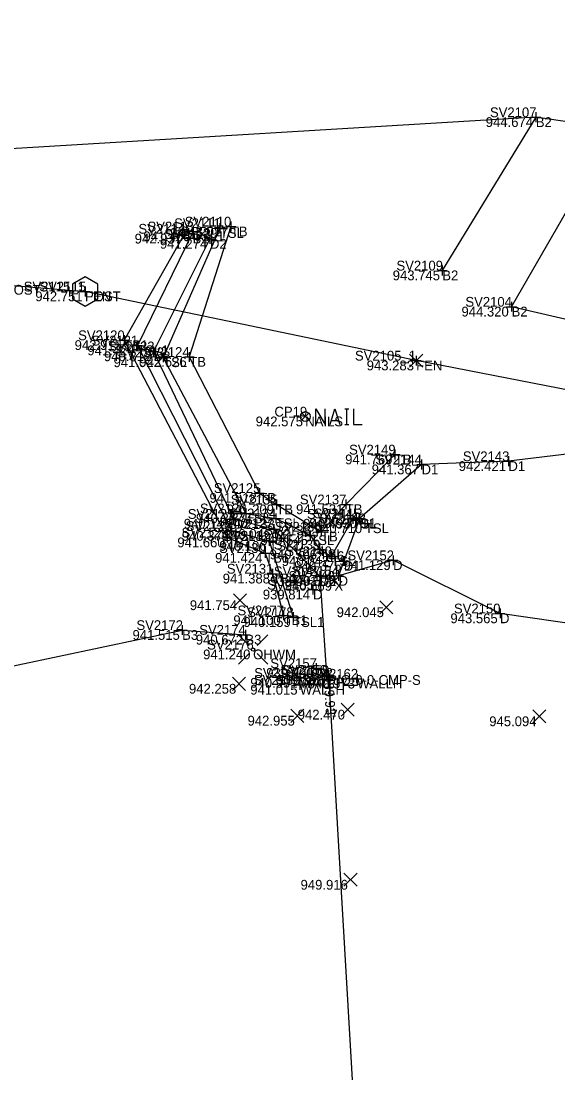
# Model space of a CAD drawing. Extents: x 2065431 to 2068157, y 709104 to 709719.
# Drawn here: x 2066361.9 to 2066416.8, y 709593.7 to 709701.2 of the extents above; entities that cross this region are included whole.
import ezdxf

# ---------------------------------------------------------------- set-up
doc = ezdxf.new("R2010")
doc.units = 0
for name, color, linetype in [('_CIVIL_CONSTRUCTION', 7, 'Continuous'), ('DR_X_Headwall', 7, 'Continuous'), ('DR_X_Storm_Sewer', 7, 'Continuous'), ('DT_X_Terrain_Boundary', 7, 'Continuous'), ('RD_X_Fence', 7, 'Continuous'), ('RS_Raster1', 7, 'Continuous'), ('RW_X_CL_100_Bearings', 7, 'Continuous'), ('RW_X_CL_100_Distances', 7, 'Continuous'), ('RW_X_CL_100_Stations', 7, 'Continuous'), ('RW_X_Fee_WL', 7, 'Continuous'), ('SC_Scratch1', 7, 'Continuous'), ('SV_X_Break_Lines', 7, 'Continuous'), ('SV_X_Mon_Cells_Found', 7, 'Continuous'), ('SV_X_Text_Elevation', 7, 'Continuous'), ('SV_X_Text_Name', 7, 'Continuous'), ('SV_X_Toe_of_Slope', 7, 'Continuous'), ('SV_X_Top_of_Bank', 7, 'Continuous')]:
    doc.layers.add(name, color=color, linetype=linetype)

msp = doc.modelspace()

# ---------------------------------------------------------------- linework, layer by layer
at = {"layer": '_CIVIL_CONSTRUCTION'}
for p, q in [((2066392.86, 709634.39), (2066393.86, 709634.39)), ((2066393.36, 709634.89), (2066393.36, 709633.89)), ((2066393.36, 709634.39), (2066393.36, 709634.39))]:
    msp.add_line(p, q, dxfattribs=at)
at = {"layer": 'DR_X_Headwall'}
for p, q in [((2066391.92, 709633.37), (2066390.44, 709633.39)), ((2066391.87, 709634.08), (2066391.92, 709633.37)), ((2066394.88, 709634.04), (2066396.3, 709634.02)), ((2066394.92, 709633.33), (2066394.88, 709634.04)), ((2066396.29, 709633.31), (2066394.92, 709633.33)), ((2066396.3, 709634.02), (2066396.29, 709633.31))]:
    msp.add_line(p, q, dxfattribs=at)
msp.add_lwpolyline([(2066390.44, 709633.39), (2066390.45, 709634.1), (2066391.87, 709634.08)], dxfattribs=at)
at = {"layer": 'DR_X_Storm_Sewer'}
msp.add_line((2066393.36, 709634.39), (2066412.21, 709311.61), dxfattribs=at)
at = {"layer": 'DT_X_Terrain_Boundary'}
msp.add_lwpolyline([(2066649.44, 709584.58), (2066543.44, 709596.37), (2066510.56, 709629.51), (2066507.17, 709644.46), (2066473.93, 709666.44), (2066463.59, 709680.71), (2066437.89, 709682.56), (2066422.56, 709690.18), (2066414.56, 709691.38), (2066359.14, 709688.04), (2066325.73, 709701.2), (2066327.01, 709677.48), (2066325.95, 709651.36), (2066268.91, 709598.56), (2066231.54, 709603.08), (2066151.93, 709594.95), (2066146.99, 709595.72), (2066142.05, 709596.5), (2066137.11, 709597.27), (2066132.17, 709598.05)], dxfattribs=at)
at = {"layer": 'RD_X_Fence'}
for points in [[(2066327.01, 709677.48), (2066360.29, 709674.25), (2066368.48, 709673.58)], [(2066507.17, 709644.46), (2066476.5, 709650.02), (2066424.89, 709662.13), (2066402.33, 709666.52), (2066368.48, 709673.58)]]:
    msp.add_lwpolyline(points, dxfattribs=at)
at = {"layer": 'RS_Raster1'}
for p, q in [((2066414.06, 709691.38), (2066415.06, 709691.38)), ((2066414.56, 709691.88), (2066414.56, 709690.88)), ((2066414.56, 709691.38), (2066414.56, 709691.38)), ((2066382.26, 709680.55), (2066382.26, 709679.55)), ((2066383.38, 709680.71), (2066383.38, 709679.71)), ((2066378.15, 709679.48), (2066379.15, 709679.48)), ((2066378.65, 709679.98), (2066378.65, 709678.98)), ((2066378.65, 709679.48), (2066378.65, 709679.48)), ((2066379.02, 709679.71), (2066380.02, 709679.71)), ((2066379.52, 709680.21), (2066379.52, 709679.21)), ((2066379.52, 709679.71), (2066379.52, 709679.71)), ((2066381.25, 709679.45), (2066381.25, 709678.45)), ((2066381.76, 709680.05), (2066382.76, 709680.05)), ((2066382.26, 709680.05), (2066382.26, 709680.05)), ((2066382.88, 709680.21), (2066383.88, 709680.21)), ((2066383.38, 709680.21), (2066383.38, 709680.21)), ((2066380.75, 709678.95), (2066381.75, 709678.95)), ((2066381.25, 709678.95), (2066381.25, 709678.95)), ((2066405, 709676.22), (2066405, 709675.22)), ((2066404.5, 709675.72), (2066405.5, 709675.72)), ((2066405, 709675.72), (2066405, 709675.72)), ((2066368.48, 709674.08), (2066368.48, 709673.08)), ((2066367.98, 709673.58), (2066368.98, 709673.58)), ((2066368.48, 709673.58), (2066368.48, 709673.58)), ((2066411.58, 709672.02), (2066412.58, 709672.02)), ((2066412.08, 709672.52), (2066412.08, 709671.52)), ((2066412.08, 709672.02), (2066412.08, 709672.02)), ((2066372.48, 709669.1), (2066372.48, 709668.1)), ((2066371.98, 709668.6), (2066372.98, 709668.6)), ((2066372.48, 709668.6), (2066372.48, 709668.6)), ((2066373.33, 709668.06), (2066374.33, 709668.06)), ((2066373.83, 709668.56), (2066373.83, 709667.56)), ((2066373.83, 709668.06), (2066373.83, 709668.06)), ((2066375.49, 709667.96), (2066375.49, 709666.96)), ((2066374.99, 709667.46), (2066375.99, 709667.46)), ((2066375.49, 709667.46), (2066375.49, 709667.46)), ((2066375.96, 709666.85), (2066376.96, 709666.85)), ((2066376.46, 709667.35), (2066376.46, 709666.35)), ((2066376.46, 709666.85), (2066376.46, 709666.85)), ((2066378.63, 709666.89), (2066379.63, 709666.89)), ((2066379.13, 709667.39), (2066379.13, 709666.39)), ((2066379.13, 709666.89), (2066379.13, 709666.89)), ((2066402.33, 709667.02), (2066402.33, 709666.02)), ((2066401.83, 709666.52), (2066402.83, 709666.52)), ((2066402.33, 709666.52), (2066402.33, 709666.52)), ((2066399.65, 709656.92), (2066400.65, 709656.92)), ((2066400.15, 709657.42), (2066400.15, 709656.42)), ((2066400.15, 709656.92), (2066400.15, 709656.92)), ((2066402.38, 709655.9), (2066403.38, 709655.9)), ((2066402.88, 709656.4), (2066402.88, 709655.4)), ((2066402.88, 709655.9), (2066402.88, 709655.9)), ((2066411.26, 709656.24), (2066412.26, 709656.24)), ((2066411.76, 709656.74), (2066411.76, 709655.74)), ((2066411.76, 709656.24), (2066411.76, 709656.24)), ((2066385.8, 709652.99), (2066386.8, 709652.99)), ((2066386.3, 709653.49), (2066386.3, 709652.49)), ((2066386.3, 709652.99), (2066386.3, 709652.99)), ((2066387.54, 709651.81), (2066388.54, 709651.81)), ((2066388.04, 709652.31), (2066388.04, 709651.31)), ((2066388.04, 709651.81), (2066388.04, 709651.81)), ((2066394.63, 709651.83), (2066395.63, 709651.83)), ((2066395.13, 709652.33), (2066395.13, 709651.33)), ((2066395.13, 709651.83), (2066395.13, 709651.83)), ((2066383.67, 709650.85), (2066383.67, 709649.85)), ((2066384.42, 709650.91), (2066385.42, 709650.91)), ((2066384.92, 709651.41), (2066384.92, 709650.41)), ((2066384.92, 709650.91), (2066384.92, 709650.91)), ((2066387.98, 709650.9), (2066387.98, 709649.9)), ((2066395.84, 709650.85), (2066395.84, 709649.85)), ((2066396.53, 709650.9), (2066396.53, 709649.9)), ((2066383.17, 709650.35), (2066384.17, 709650.35)), ((2066383.46, 709649.61), (2066383.46, 709648.61)), ((2066383.67, 709650.35), (2066383.67, 709650.35)), ((2066387.48, 709650.4), (2066388.48, 709650.4)), ((2066387.78, 709649.81), (2066387.78, 709648.81)), ((2066387.98, 709650.4), (2066387.98, 709650.4)), ((2066392.6, 709649.54), (2066392.6, 709648.54)), ((2066395.34, 709650.35), (2066396.34, 709650.35)), ((2066395.84, 709650.35), (2066395.84, 709650.35)), ((2066396.03, 709650.4), (2066397.03, 709650.4)), ((2066396.53, 709650.4), (2066396.53, 709650.4)), ((2066396.59, 709649.89), (2066397.59, 709649.89)), ((2066397.09, 709650.39), (2066397.09, 709649.39)), ((2066397.09, 709649.89), (2066397.09, 709649.89)), ((2066382.52, 709648.44), (2066383.52, 709648.44)), ((2066382.96, 709649.11), (2066383.96, 709649.11)), ((2066383.02, 709648.94), (2066383.02, 709647.94)), ((2066383.02, 709648.44), (2066383.02, 709648.44)), ((2066383.46, 709649.11), (2066383.46, 709649.11)), ((2066387.28, 709649.31), (2066388.28, 709649.31)), ((2066387.3, 709648.59), (2066387.3, 709647.59)), ((2066387.78, 709649.31), (2066387.78, 709649.31)), ((2066391, 709648.67), (2066392, 709648.67)), ((2066391.5, 709649.17), (2066391.5, 709648.17)), ((2066391.5, 709648.67), (2066391.5, 709648.67)), ((2066392.1, 709649.04), (2066393.1, 709649.04)), ((2066392.6, 709649.04), (2066392.6, 709649.04)), ((2066386.8, 709648.09), (2066387.8, 709648.09)), ((2066386.89, 709647.36), (2066386.89, 709646.36)), ((2066387.3, 709648.09), (2066387.3, 709648.09)), ((2066391.95, 709647.22), (2066392.95, 709647.22)), ((2066392.45, 709647.72), (2066392.45, 709646.72)), ((2066392.45, 709647.22), (2066392.45, 709647.22)), ((2066386.39, 709646.86), (2066387.39, 709646.86)), ((2066386.89, 709646.86), (2066386.89, 709646.86)), ((2066393.16, 709646.54), (2066394.16, 709646.54)), ((2066393.66, 709647.04), (2066393.66, 709646.04)), ((2066393.66, 709646.54), (2066393.66, 709646.54)), ((2066394.93, 709646.54), (2066394.93, 709645.54)), ((2066399.47, 709646.12), (2066400.47, 709646.12)), ((2066399.97, 709646.62), (2066399.97, 709645.62)), ((2066399.97, 709646.12), (2066399.97, 709646.12)), ((2066387.65, 709645.25), (2066387.65, 709644.25)), ((2066394.43, 709646.04), (2066395.43, 709646.04)), ((2066394.93, 709646.04), (2066394.93, 709646.04)), ((2066387.15, 709644.75), (2066388.15, 709644.75)), ((2066387.65, 709644.75), (2066387.65, 709644.75)), ((2066391.97, 709644.49), (2066392.97, 709644.49)), ((2066392.47, 709644.99), (2066392.47, 709643.99)), ((2066392.47, 709644.49), (2066392.47, 709644.49)), ((2066393.9, 709644.52), (2066394.9, 709644.52)), ((2066394.4, 709645.02), (2066394.4, 709644.02)), ((2066394.4, 709644.52), (2066394.4, 709644.52)), ((2066391.28, 709643.12), (2066392.28, 709643.12)), ((2066391.78, 709643.62), (2066391.78, 709642.62)), ((2066391.78, 709643.12), (2066391.78, 709643.12)), ((2066388.76, 709640.99), (2066388.76, 709639.99)), ((2066389.75, 709640.81), (2066389.75, 709639.81)), ((2066410.9, 709641.19), (2066410.9, 709640.19)), ((2066388.26, 709640.49), (2066389.26, 709640.49)), ((2066388.76, 709640.49), (2066388.76, 709640.49)), ((2066389.25, 709640.31), (2066390.25, 709640.31)), ((2066389.75, 709640.31), (2066389.75, 709640.31)), ((2066410.4, 709640.69), (2066411.4, 709640.69)), ((2066410.9, 709640.69), (2066410.9, 709640.69)), ((2066377.9, 709638.99), (2066378.9, 709638.99)), ((2066378.4, 709639.49), (2066378.4, 709638.49)), ((2066378.4, 709638.99), (2066378.4, 709638.99)), ((2066384.87, 709639.01), (2066384.87, 709638.01)), ((2066384.37, 709638.51), (2066385.37, 709638.51)), ((2066384.87, 709638.51), (2066384.87, 709638.51)), ((2066392.11, 709635.6), (2066392.11, 709634.6)), ((2066390.45, 709634.6), (2066390.45, 709633.6)), ((2066391.61, 709635.1), (2066392.61, 709635.1)), ((2066392.11, 709635.1), (2066392.11, 709635.1)), ((2066392.65, 709634.42), (2066393.65, 709634.42)), ((2066393.15, 709634.92), (2066393.15, 709633.92)), ((2066393.15, 709634.42), (2066393.15, 709634.42)), ((2066393.33, 709634.43), (2066393.33, 709633.43)), ((2066396.3, 709634.52), (2066396.3, 709633.52)), ((2066389.94, 709633.39), (2066390.94, 709633.39)), ((2066389.95, 709634.1), (2066390.95, 709634.1)), ((2066390.44, 709633.89), (2066390.44, 709632.89)), ((2066390.44, 709633.39), (2066390.44, 709633.39)), ((2066390.45, 709634.1), (2066390.45, 709634.1)), ((2066392.83, 709633.93), (2066393.83, 709633.93)), ((2066393.33, 709633.93), (2066393.33, 709633.93)), ((2066395.8, 709634.02), (2066396.8, 709634.02)), ((2066396.3, 709634.02), (2066396.3, 709634.02))]:
    msp.add_line(p, q, dxfattribs=at)
at = {"layer": 'RW_X_CL_100_Bearings'}
for p, q in [((2066401.66, 709665.86), (2066403, 709667.19)), ((2066401.66, 709667.19), (2066403, 709665.86)), ((2066393.3, 709643.35), (2066394.64, 709644.68)), ((2066393.3, 709644.68), (2066394.64, 709643.35)), ((2066383.64, 709641.36), (2066384.97, 709642.7)), ((2066383.64, 709642.7), (2066384.97, 709641.36)), ((2066398.6, 709640.64), (2066399.94, 709641.97)), ((2066398.6, 709641.97), (2066399.94, 709640.64)), ((2066383.54, 709632.83), (2066384.87, 709634.16)), ((2066383.54, 709634.16), (2066384.87, 709632.83)), ((2066394.67, 709630.18), (2066396, 709631.52)), ((2066394.67, 709631.52), (2066396, 709630.18)), ((2066389.5, 709629.56), (2066390.83, 709630.9)), ((2066389.5, 709630.9), (2066390.83, 709629.56)), ((2066414.26, 709629.5), (2066415.59, 709630.84)), ((2066414.26, 709630.84), (2066415.59, 709629.5)), ((2066394.94, 709612.81), (2066396.28, 709614.14)), ((2066394.94, 709614.14), (2066396.28, 709612.81))]:
    msp.add_line(p, q, dxfattribs=at)
at = {"layer": 'RW_X_CL_100_Distances'}
msp.add_lwpolyline([(2066367.18, 709672.83), (2066368.48, 709672.08), (2066369.77, 709672.83), (2066369.77, 709674.33), (2066368.48, 709675.08), (2066367.18, 709674.33), (2066367.18, 709672.83)], dxfattribs=at)
at = {"layer": 'RW_X_CL_100_Stations'}
for p, q in [((2066390.64, 709661.15), (2066391.34, 709660.45)), ((2066390.64, 709660.45), (2066391.34, 709661.15)), ((2066384.15, 709638.51), (2066385.25, 709637.41)), ((2066386.08, 709637.41), (2066387.17, 709638.51)), ((2066384.15, 709635.49), (2066385.25, 709636.58)), ((2066386.08, 709636.58), (2066387.17, 709635.49))]:
    msp.add_line(p, q, dxfattribs=at)
for points in [[(2066392.08, 709659.99), (2066392.08, 709661.59), (2066393.02, 709659.99), (2066393.02, 709661.59)], [(2066393.53, 709659.99), (2066394.03, 709661.59), (2066394.52, 709659.99)], [(2066395.03, 709661.59), (2066395.43, 709661.59)], [(2066395.23, 709659.99), (2066395.23, 709661.59)], [(2066395.93, 709661.59), (2066395.93, 709659.99), (2066396.8, 709659.99)], [(2066394.4, 709660.37), (2066393.65, 709660.37)], [(2066395.03, 709659.99), (2066395.43, 709659.99)]]:
    msp.add_lwpolyline(points, dxfattribs=at)
for centre, radius in [((2066390.99, 709660.8), 0.5), ((2066385.66, 709637), 0.17)]:
    msp.add_circle(centre, radius, dxfattribs=at)
at = {"layer": 'RW_X_Fee_WL'}
for points in [[(2066381.25, 709678.95), (2066375.49, 709667.46), (2066383.67, 709650.35), (2066387.78, 709649.31), (2066392.47, 709644.49)], [(2066445.49, 709660.3), (2066411.76, 709656.24), (2066402.88, 709655.9), (2066396.53, 709650.4), (2066394.93, 709646.04), (2066394.4, 709644.52)], [(2066834.34, 709517.99), (2066792.15, 709523.14), (2066747.37, 709529.6), (2066701.7, 709535.47), (2066656.28, 709541.34), (2066614.98, 709547.01), (2066577.22, 709555.89), (2066538.15, 709580.88), (2066497.57, 709596.35), (2066445.11, 709628.08), (2066445.1, 709628.08), (2066425.53, 709638.57), (2066410.9, 709640.69), (2066399.97, 709646.12), (2066394.4, 709644.52), (2066392.47, 709644.49), (2066393.15, 709634.42)]]:
    msp.add_lwpolyline(points, dxfattribs=at)
at = {"layer": 'SV_X_Break_Lines'}
for points in [[(2066463.59, 709680.71), (2066432.87, 709667.22), (2066412.08, 709672.02), (2066422.56, 709690.18), (2066414.56, 709691.38), (2066405, 709675.72)], [(2066333.38, 709627.46), (2066357.42, 709634.54), (2066378.4, 709638.99), (2066384.87, 709638.51)]]:
    msp.add_lwpolyline(points, dxfattribs=at)
at = {"layer": 'SV_X_Toe_of_Slope'}
for points in [[(2066379.52, 709679.71), (2066373.83, 709668.06), (2066383.46, 709649.11), (2066387.3, 709648.09), (2066389.75, 709640.31)], [(2066382.26, 709680.05), (2066376.46, 709666.85), (2066384.92, 709650.91), (2066387.98, 709650.4), (2066391.5, 709648.67), (2066392.45, 709647.22), (2066393.66, 709646.54), (2066395.84, 709650.35)]]:
    msp.add_lwpolyline(points, dxfattribs=at)
at = {"layer": 'SV_X_Top_of_Bank'}
for points in [[(2066378.65, 709679.48), (2066372.48, 709668.6), (2066383.02, 709648.44), (2066386.89, 709646.86), (2066387.65, 709644.75), (2066388.76, 709640.49)], [(2066383.38, 709680.21), (2066379.13, 709666.89), (2066386.3, 709652.99), (2066388.04, 709651.81), (2066392.6, 709649.04), (2066395.13, 709651.83), (2066400.15, 709656.92)]]:
    msp.add_lwpolyline(points, dxfattribs=at)

# ---------------------------------------------------------------- texts
at = {"layer": 'SC_Scratch1'}
msp.add_text("939.93'", height=1, rotation=273.3419, dxfattribs=at).set_placement((2066392.86, 709634.36))
at = {"layer": 'SV_X_Mon_Cells_Found'}
for s, p in [('SV2107', (2066409.87, 709691.38)), ('SV2113', (2066374.86, 709679.71)), ('SV2111', (2066377.59, 709680.05)), ('SV2110', (2066378.67, 709680.21)), ('SV2114', (2066373.93, 709679.48)), ('SV2112', (2066376.58, 709678.95)), ('SV2109', (2066400.31, 709675.72)), ('SV2115_1', (2066362.21, 709673.58)), ('SV2115', (2066363.81, 709673.58)), ('SV2104', (2066407.36, 709672.02)), ('SV2120', (2066367.77, 709668.6)), ('SV2121', (2066369.15, 709668.06)), ('SV2122', (2066370.82, 709667.46)), ('SV2123', (2066371.8, 709666.85)), ('SV2124', (2066374.41, 709666.89)), ('SV2105_1', (2066396.07, 709666.52)), ('CP19', (2066387.84, 709660.8)), ('SV2149', (2066395.47, 709656.92)), ('SV2144', (2066398.15, 709655.9)), ('SV2143', (2066407.1, 709656.24)), ('SV2125', (2066381.64, 709652.99)), ('SV2135', (2066383.37, 709651.81)), ('SV2137', (2066390.44, 709651.83)), ('SV2126', (2066380.22, 709650.91)), ('SV2127', (2066378.98, 709650.35)), ('SV2134', (2066383.26, 709650.4)), ('SV2141', (2066391.16, 709650.35)), ('SV2145', (2066391.86, 709650.4)), ('SV2142', (2066392.42, 709649.89)), ('SV2129', (2066378.34, 709648.44)), ('SV2128', (2066378.76, 709649.11)), ('SV2133', (2066383.11, 709649.31)), ('SV2138', (2066386.8, 709648.67)), ('SV2136', (2066387.9, 709649.04)), ('SV2132', (2066382.63, 709648.09)), ('SV2130', (2066382.18, 709646.86)), ('SV2139', (2066387.77, 709647.22)), ('SV2140', (2066388.95, 709646.54)), ('SV2146', (2066390.23, 709646.04)), ('SV2152', (2066395.3, 709646.12)), ('SV2131', (2066382.97, 709644.75)), ('SV2147', (2066387.78, 709644.49)), ('SV2154', (2066389.67, 709644.52)), ('SV2155', (2066387.11, 709643.12)), ('SV2148', (2066389.27, 709644.01)), ('SV2177', (2066384.06, 709640.49)), ('SV2178', (2066385.05, 709640.31)), ('SV2150', (2066406.19, 709640.69)), ('SV2172', (2066373.73, 709638.99)), ('SV2174', (2066380.15, 709638.51)), ('SV2176', (2066380.96, 709637)), ('SV2157', (2066387.42, 709635.1)), ('SV2156', (2066388.45, 709634.42)), ('SV2159', (2066388.68, 709634.39)), ('SV2160', (2066385.73, 709633.39)), ('SV2161', (2066385.77, 709634.1)), ('SV2162', (2066391.63, 709634.02))]:
    msp.add_text(s, height=1, dxfattribs=at).set_placement(p)
at = {"layer": 'SV_X_Text_Elevation'}
for s, p in [('B2', (2066414.56, 709690.38)), ('TB1', (2066378.65, 709678.48)), ('TSL1', (2066379.52, 709678.71)), ('TSL', (2066382.26, 709679.05)), ('TB', (2066383.38, 709679.21)), ('D2', (2066381.25, 709677.95)), ('B2', (2066405, 709674.72)), ('POST', (2066360.29, 709673.25)), ('POST', (2066368.48, 709672.58)), ('FEN', (2066368.48, 709672.58)), ('B2', (2066412.08, 709671.02)), ('TB1', (2066372.48, 709667.6)), ('TSL1', (2066373.83, 709667.06)), ('D2', (2066375.49, 709666.46)), ('TSL', (2066376.46, 709665.85)), ('TB', (2066379.13, 709665.89)), ('FEN', (2066402.33, 709665.52)), ('NAILS', (2066390.99, 709659.8)), ('TB', (2066400.15, 709655.92)), ('D1', (2066402.88, 709654.9)), ('D1', (2066411.76, 709655.24)), ('TB', (2066386.3, 709651.99)), ('TB', (2066388.04, 709650.81)), ('TB', (2066395.13, 709650.83)), ('TSL', (2066384.92, 709649.91)), ('D2', (2066383.67, 709649.35)), ('TSL', (2066387.98, 709649.4)), ('TSL', (2066395.84, 709649.35)), ('D1', (2066396.53, 709649.4)), ('TSL', (2066397.09, 709648.89)), ('TB1', (2066383.02, 709647.44)), ('TSL1', (2066383.46, 709648.11)), ('D2', (2066387.78, 709648.31)), ('TSL', (2066391.5, 709647.67)), ('TB', (2066392.6, 709648.04)), ('TSL1', (2066387.3, 709647.09)), ('TSL', (2066392.45, 709646.22)), ('TB1', (2066386.89, 709645.86)), ('TSL', (2066393.66, 709645.54)), ('D', (2066399.97, 709645.12)), ('D1', (2066394.93, 709645.04)), ('TB1', (2066387.65, 709643.75)), ('D2', (2066392.47, 709643.49)), ('X', (2066393.97, 709643.01)), ('D', (2066394.4, 709643.52)), ('D', (2066391.78, 709642.12)), ('TB1', (2066388.76, 709639.49)), ('TSL1', (2066389.75, 709639.31)), ('D', (2066410.9, 709639.69)), ('B3', (2066378.4, 709637.99)), ('B3', (2066384.87, 709637.51)), ('OHWM', (2066385.66, 709636)), ('D2', (2066392.11, 709634.1)), ('D', (2066393.15, 709633.42)), ('PIO-0-0-CMP-S', (2066393.36, 709633.39)), ('WALLH', (2066390.44, 709632.39)), ('WALLH', (2066390.45, 709633.1)), ('WALLH', (2066396.3, 709633.02))]:
    msp.add_text(s, height=1, dxfattribs=at).set_placement(p)
at = {"layer": 'SV_X_Text_Name'}
for s, p in [('944.674', (2066409.44, 709690.38)), ('942.937', (2066373.55, 709678.48)), ('941.465', (2066374.45, 709678.71)), ('941.529', (2066377.18, 709679.05)), ('943.017', (2066378.29, 709679.21)), ('941.274', (2066376.13, 709677.95)), ('943.745', (2066399.93, 709674.72)), ('942.751', (2066363.39, 709672.58)), ('942.751', (2066363.39, 709672.58)), ('944.320', (2066406.96, 709671.02)), ('942.915', (2066367.41, 709667.6)), ('941.424', (2066368.71, 709667.06)), ('940.812', (2066370.41, 709666.46)), ('941.022', (2066371.39, 709665.85)), ('942.626', (2066374.03, 709665.89)), ('943.283', (2066397.27, 709665.52)), ('943.283', (2066397.27, 709665.52)), ('942.575', (2066385.92, 709659.8)), ('941.769', (2066395.07, 709655.92)), ('941.367', (2066397.78, 709654.9)), ('942.421', (2066406.68, 709655.24)), ('941.518', (2066381.2, 709651.99)), ('941.209', (2066382.96, 709650.81)), ('941.531', (2066390.05, 709650.83)), ('940.277', (2066379.82, 709649.91)), ('940.690', (2066391.41, 709649.4)), ('940.146', (2066378.57, 709649.35)), ('940.127', (2066382.89, 709649.4)), ('940.493', (2066390.78, 709649.35)), ('940.710', (2066391.97, 709648.89)), ('941.660', (2066377.91, 709647.44)), ('940.379', (2066378.37, 709648.11)), ('940.046', (2066382.67, 709648.31)), ('940.545', (2066386.43, 709647.67)), ('941.252', (2066387.53, 709648.04)), ('940.106', (2066382.2, 709647.09)), ('940.506', (2066387.35, 709646.22)), ('941.424', (2066381.77, 709645.86)), ('940.042', (2066388.59, 709645.54)), ('941.129', (2066394.89, 709645.12)), ('940.375', (2066389.86, 709645.04)), ('941.388', (2066382.55, 709643.75)), ('939.991', (2066387.39, 709643.49)), ('940.669', (2066388.89, 709643.01)), ('940.378', (2066389.29, 709643.52)), ('939.814', (2066386.65, 709642.12)), ('941.754', (2066379.19, 709641.03)), ('942.045', (2066394.2, 709640.31)), ('941.100', (2066383.64, 709639.49)), ('940.159', (2066384.67, 709639.31)), ('943.565', (2066405.83, 709639.69)), ('941.515', (2066373.33, 709637.99)), ('940.672', (2066379.8, 709637.51)), ('941.240', (2066380.55, 709636)), ('939.990', (2066387, 709634.1)), ('939.898', (2066388.05, 709633.42)), ('939.926', (2066388.25, 709633.39)), ('942.258', (2066379.1, 709632.49)), ('940.991', (2066385.37, 709633.1)), ('941.015', (2066385.37, 709632.39)), ('940.973', (2066391.24, 709633.02)), ('942.955', (2066385.09, 709629.23)), ('942.470', (2066390.22, 709629.85)), ('945.094', (2066409.8, 709629.17)), ('949.916', (2066390.51, 709612.47))]:
    msp.add_text(s, height=1, dxfattribs=at).set_placement(p)

doc.saveas('drawing.dxf')
